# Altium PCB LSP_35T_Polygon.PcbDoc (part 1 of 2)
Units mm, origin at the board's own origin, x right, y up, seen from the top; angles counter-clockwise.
Board outline 152.4 x 101.6 mm, 4 copper layers (Top Layer, Mid-Layer 1, Mid-Layer 3, Bottom Layer); 138 components, 96 nets, 424 pads, 124 vias.
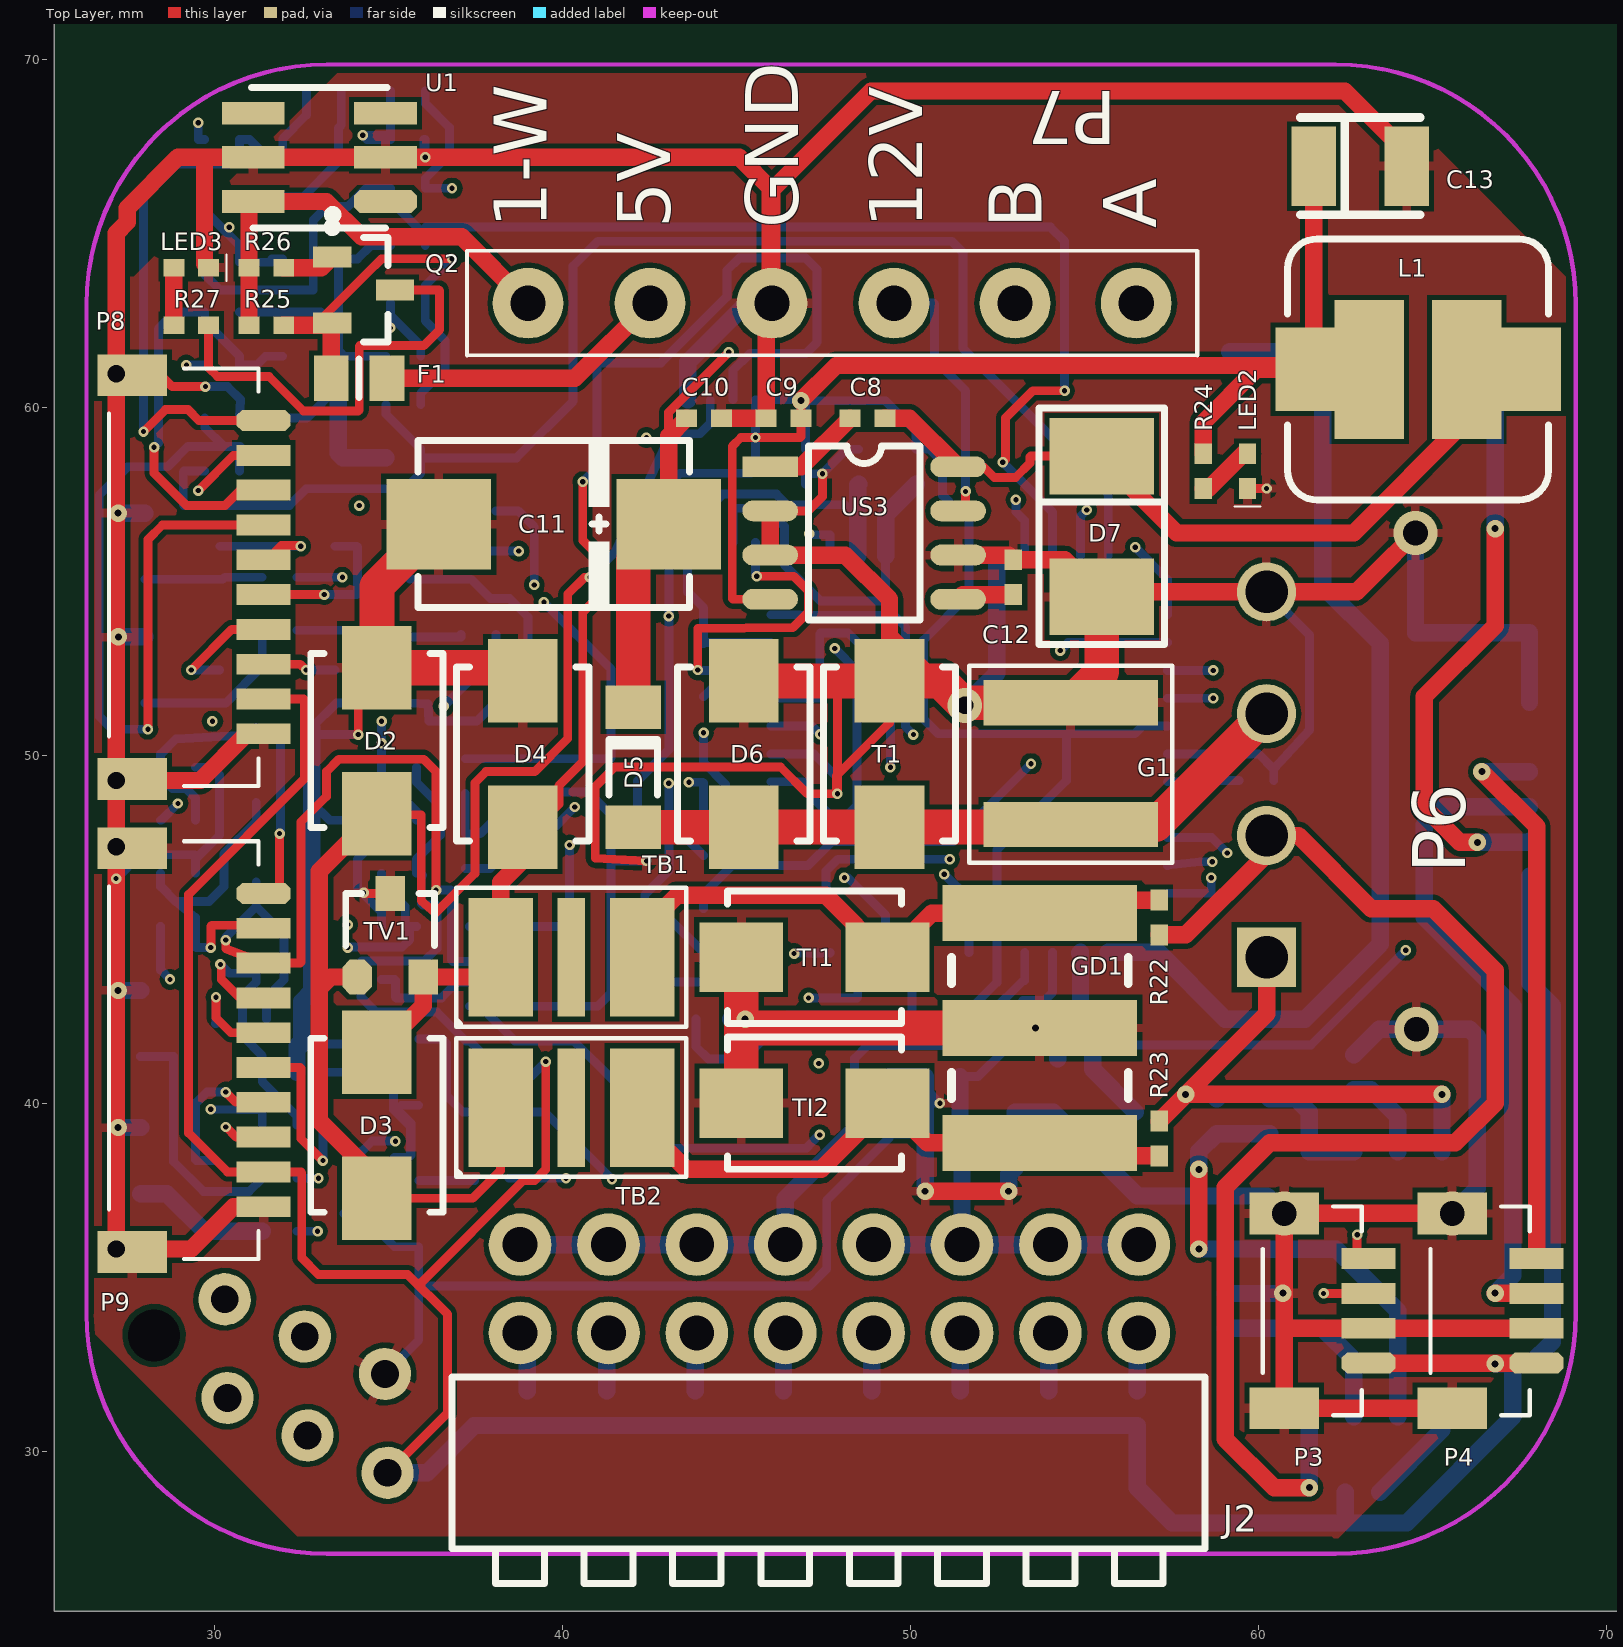
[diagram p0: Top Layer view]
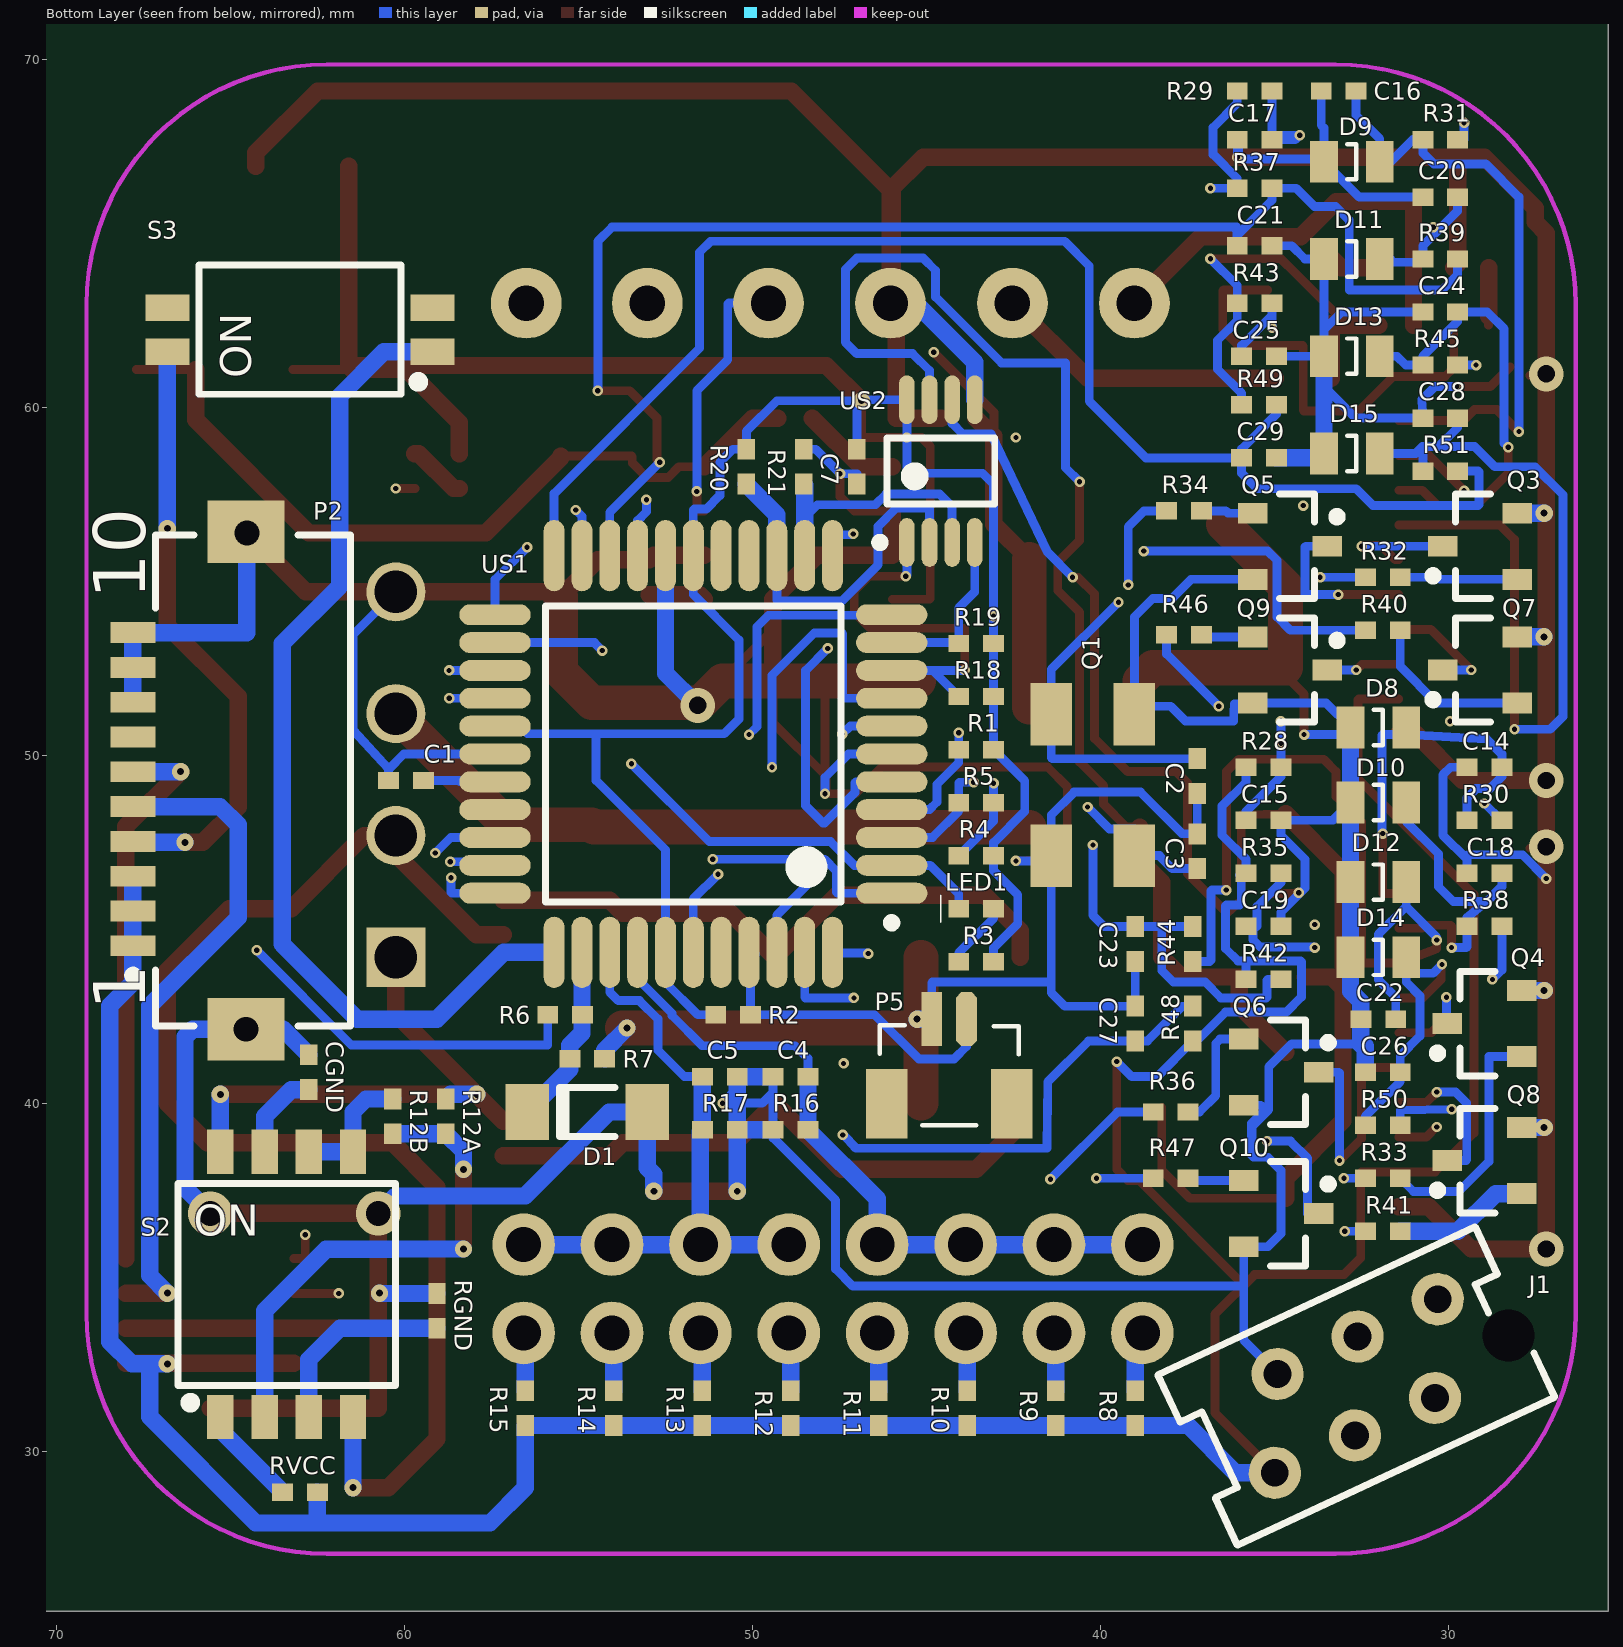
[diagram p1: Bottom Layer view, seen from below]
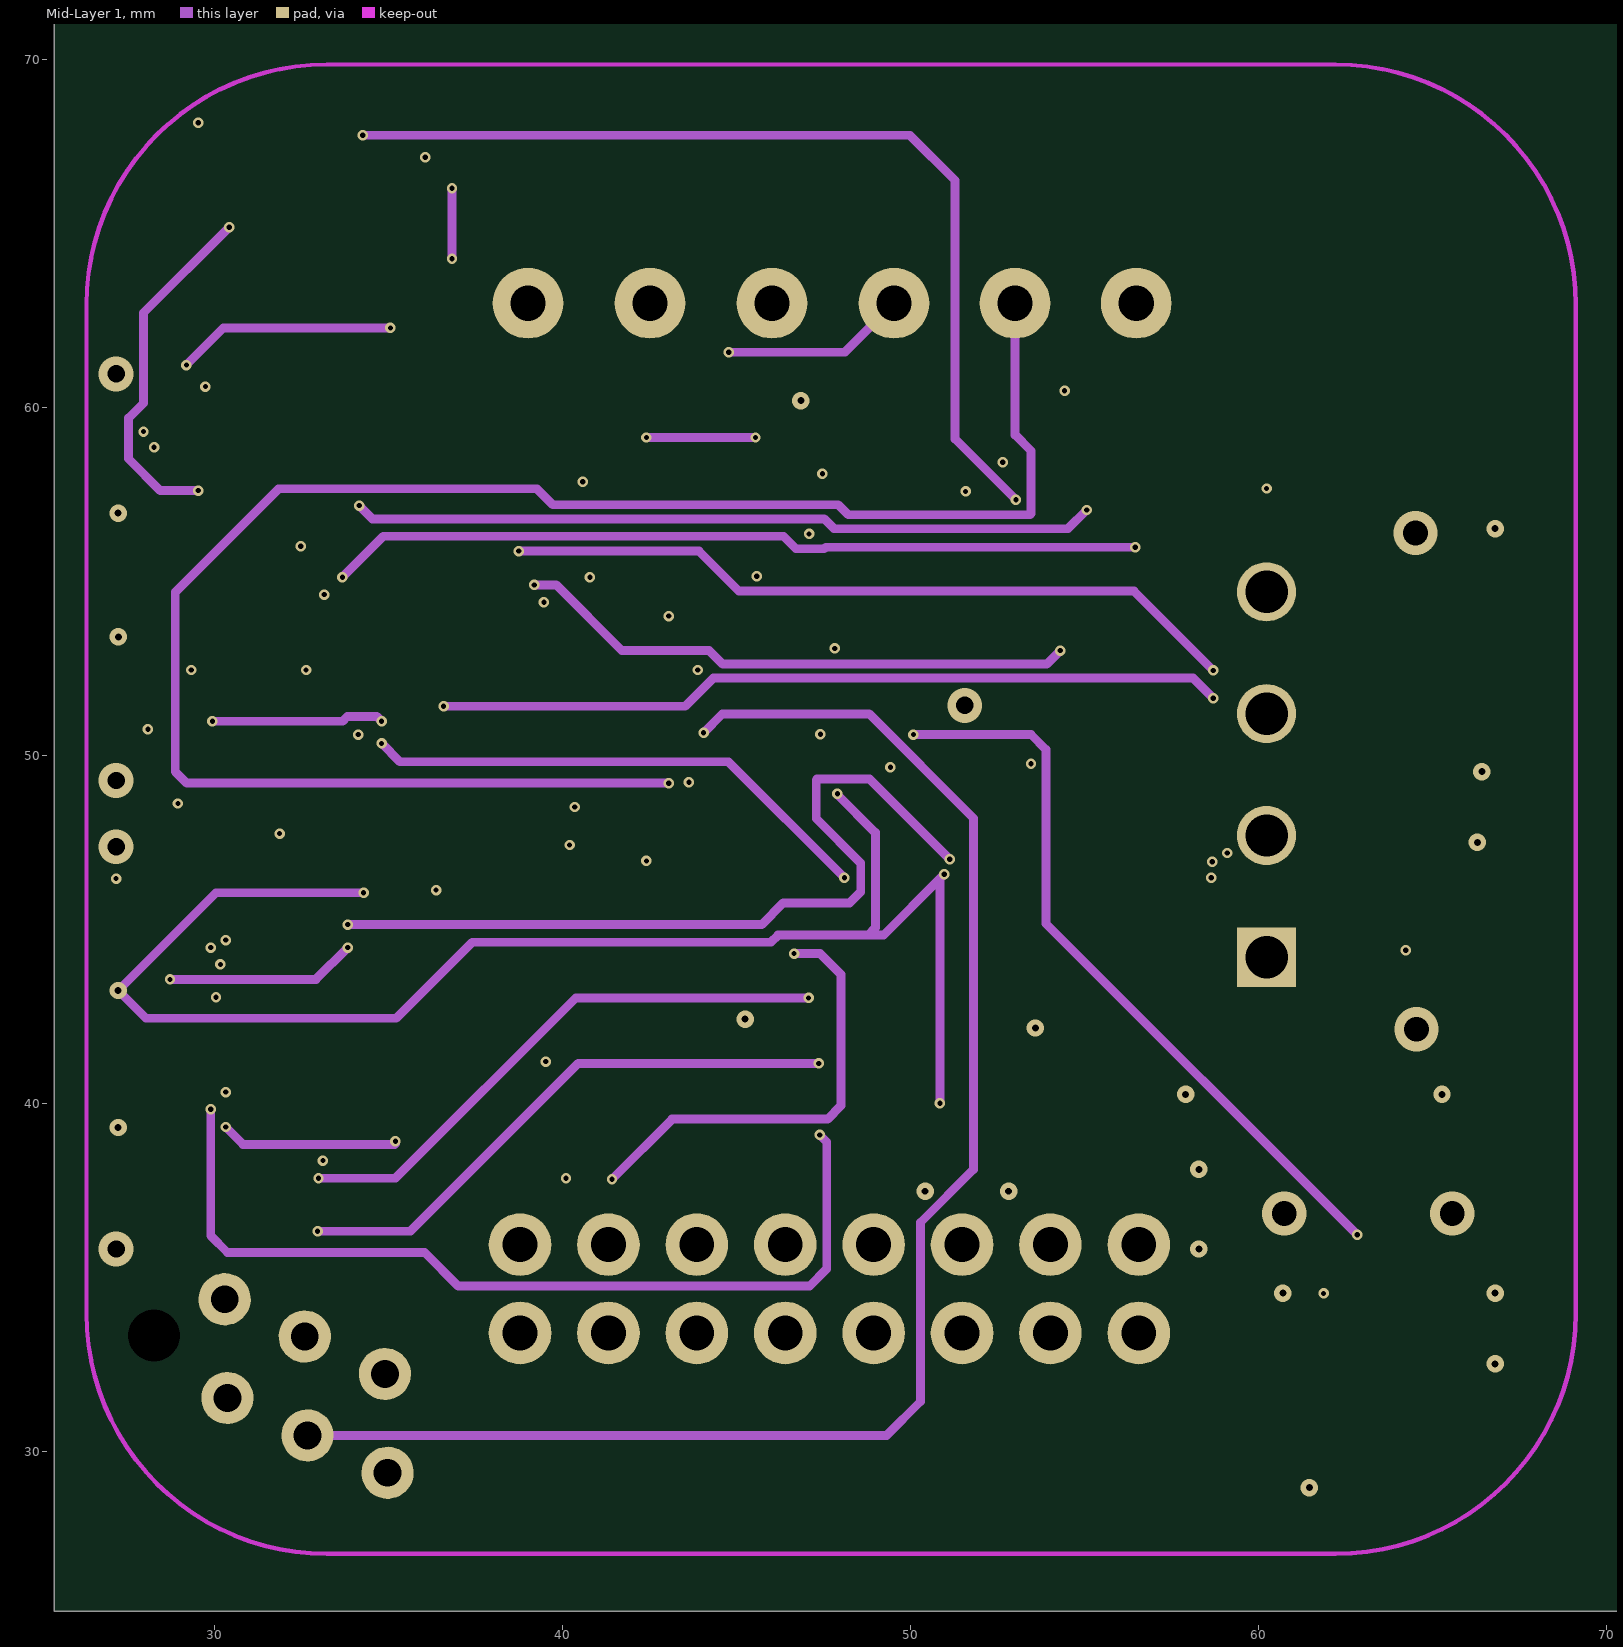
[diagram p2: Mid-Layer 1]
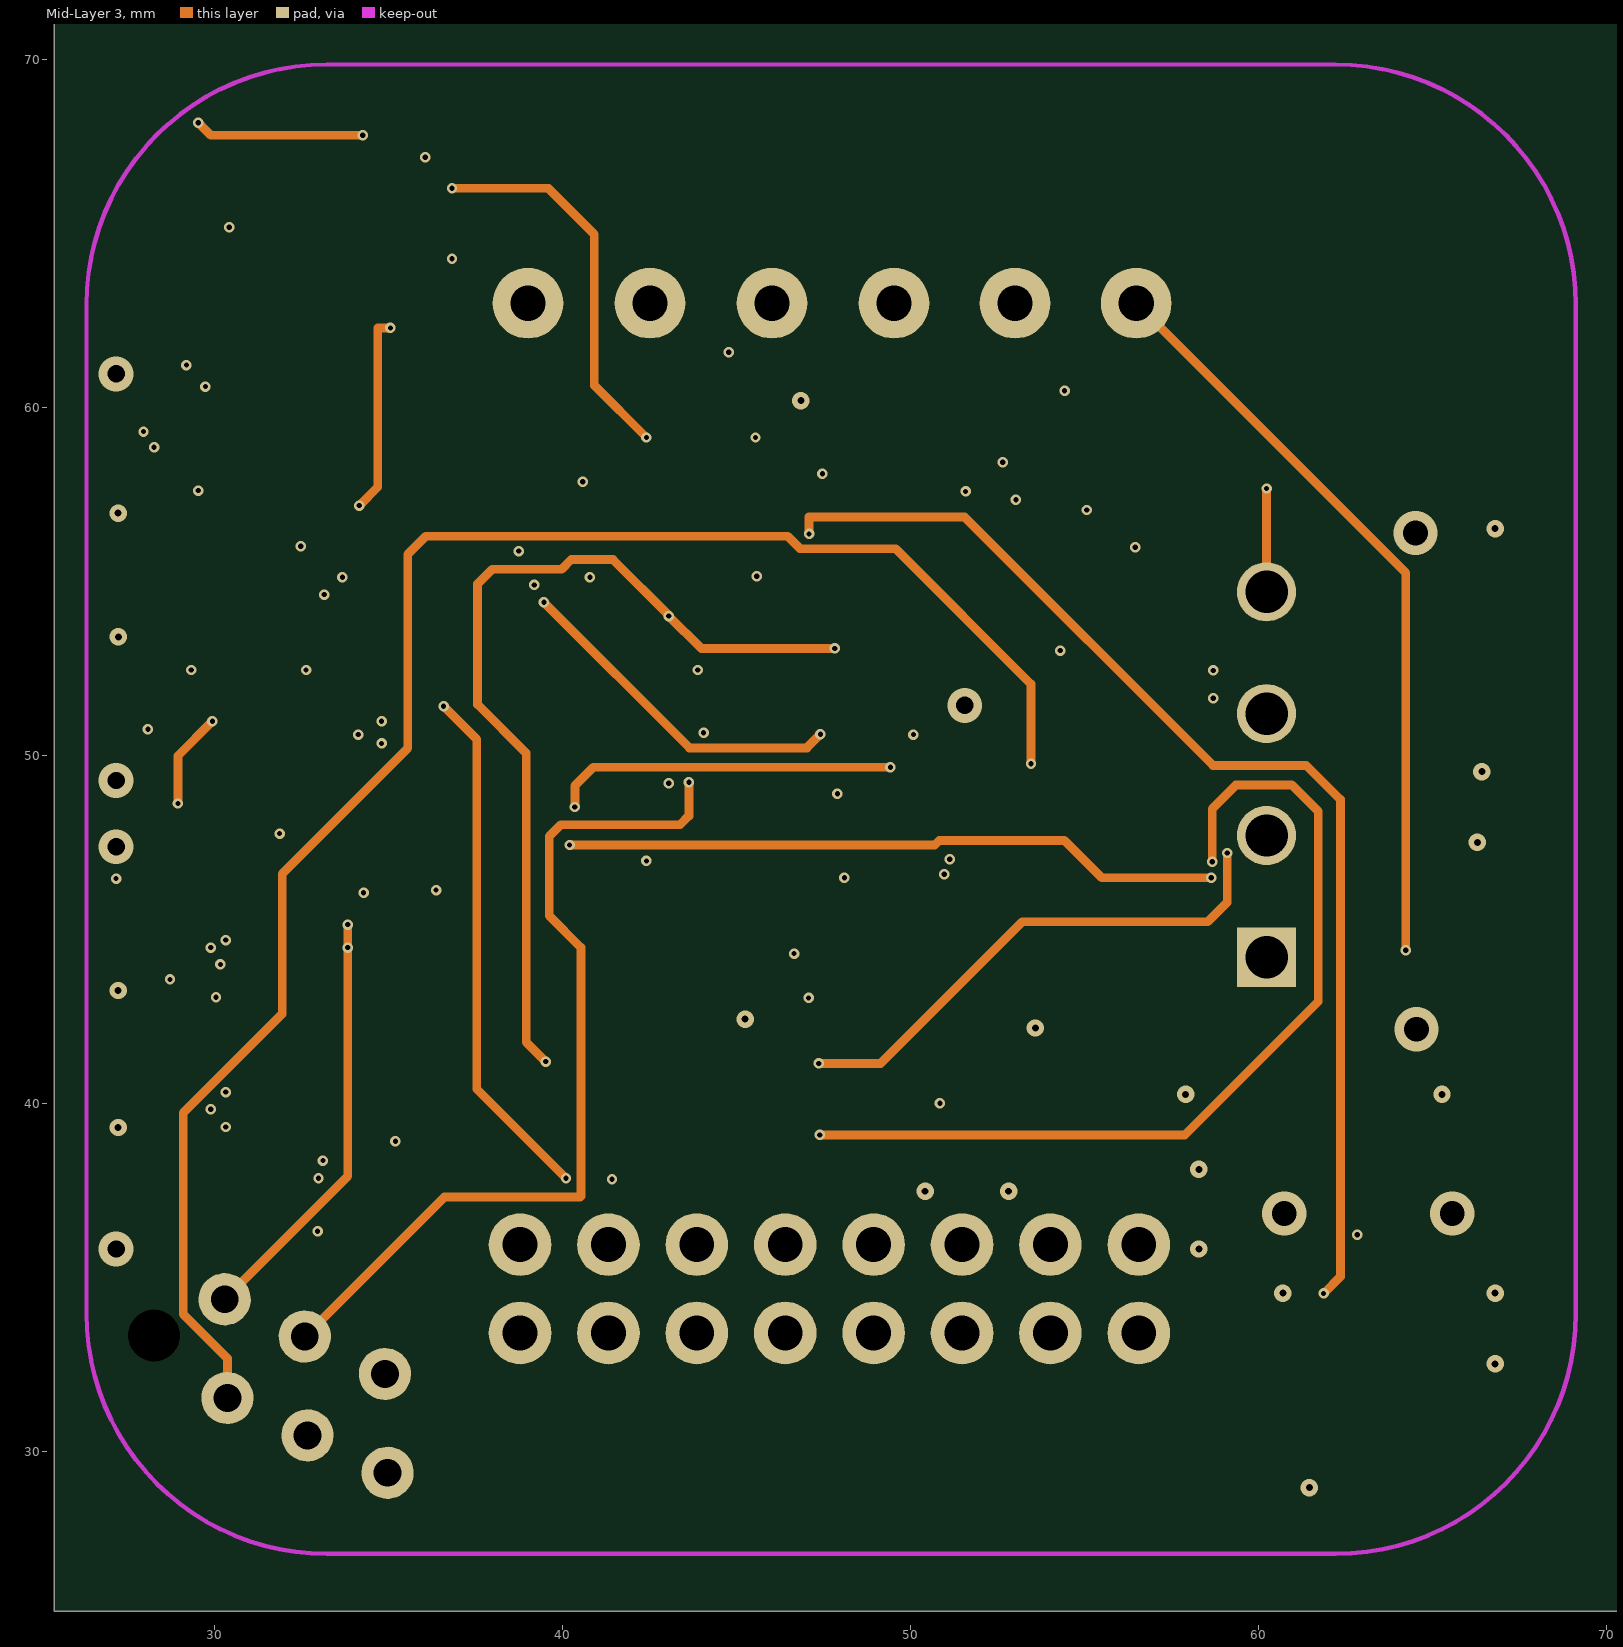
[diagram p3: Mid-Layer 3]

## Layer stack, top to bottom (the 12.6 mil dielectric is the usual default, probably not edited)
Top Layer: signal copper 0.0356
Dielectric: dielectric 0.32, FR-4, Dk 4.8
Mid-Layer 1: signal copper 0.0356
Dielectric: dielectric 0.32, FR-4, Dk 4.8
Mid-Layer 3: signal copper 0.0356
Dielectric: dielectric 0.32, FR-4, Dk 4.8
Bottom Layer: signal copper 0.0356

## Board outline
25.4,25.4 177.8,25.4 177.8,127 25.4,127

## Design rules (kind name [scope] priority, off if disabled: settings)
Clearance [All] p1: gap=0.15
ComponentClearance [All] p1: gap=0.15 collisioncheckmode=3 verticalgap=0.254 showdistances=FALSE
MinimumSolderMaskSliver [All] p1: minsoldermaskwidth=0.15
PolygonConnect [All] p1: connectstyle=Relief reliefconductorwidth=0.254 reliefentries=4 polygonreliefangle="90 Angle"
RoutingVias [All] p1: holewidth=0.15 width=0.3 viastyle="Through Hole" minholewidth=0.15 minwidth=0.3 maxholewidth=1.2 maxwidth=1.5
SilkToSilkClearance [All] p1: silktosilkclearance=0
SilkscreenOverComponentPads [All] p1: minsilkscreentomaskgap=0
SolderMaskExpansion [All] p1: expansion=0.1
Width [All] p1: maxlimit=1 minlimit=0.15 preferedwidth=0.254
24 further rules are at their usual default settings.

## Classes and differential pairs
component class LSP_DIO: C14 C15 C16 C17 C18 C19 C20 C21 C22 C23 C24 C25 C26 C27 C28 C29 D8 D9 D10 D11 D12 D13 D14 D15 P8 P9 Q3 Q4 Q5 Q6 Q7 Q8 Q9 Q10 R28 R29 R30 R31 R32 R33 R34 R35 R36 R37 R38 R39 R40 R41 R42 R43 R44 R45 R46 R47 R48 R49 R50 R51
component class ZASILACZ: C8 C9 C10 C11 C12 C13 D5 D6 D7 G1 L1 LED2 R24 T1 US3
component class RS485: C7 CGND D2 D3 D4 GD1 R12A R12B R18 R19 R20 R21 R22 R23 RGND RVCC S2 TB1 TB2 TI1 TI2 TV1 US2
component class LSP_35T: C1 C2 C3 D1 J1 LED1 P2 P3 P4 P5 P6 Q1 R1 R2 R3 R4 R5 R6 R7 S3 US1
component class Adres: C4 C5 J2 R8 R9 R10 R11 R12 R13 R14 R15 R16 R17
component class 1-Wire: F1 LED3 P7 Q2 R25 R26 R27 U1

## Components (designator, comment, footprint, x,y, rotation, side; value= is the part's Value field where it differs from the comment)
C1 "10nF/16V (X7R)" 0402 59.944,49.276 r0 bottom
C2 "15pF/16V (NPO)" 0402 37.211,49.403 r90 bottom
C3 "15pF/16V (NPO)" 0402 37.211,47.244 r270 bottom
C4 "100nF/16V (X7R)" 0402 48.895,40.767 r0 bottom
C5 "100nF/16V (X7R)" 0402 50.927,40.767 r180 bottom
C7 "100nF/16V (X7R)" 0402 46.99,58.293 r90 bottom
C8 "10nF/50V (X7R)" 0402 48.768,59.69 r0 top
C9 "100nF/25V (X7R)" 0402 46.355,59.69 r0 top
C10 "100nF/50V (X7R)" 0402 44.069,59.69 r180 top
C11 "22uF/35V" SMD_C_TANTAL-D 43.053,56.642 r180 top
C12 "100nF/50V (X7R)" 0402 52.959,55.118 r270 top
C13 "T491B226M010AT" TANTAL-B 61.595,66.929 r0 top
C14 "Cap Semi" 0402 28.956,49.657 r180 bottom
C15 "Cap Semi" 0402 35.306,48.133 r0 bottom
C16 "Cap Semi" 0402 33.147,69.088 r180 bottom
C17 "Cap Semi" 0402 35.56,67.691 r180 bottom
C18 "Cap Semi" 0402 28.956,46.609 r180 bottom
C19 "Cap Semi" 0402 35.306,45.085 r0 bottom
C20 "Cap Semi" 0402 30.226,66.04 r180 bottom
C21 "Cap Semi" 0402 35.56,64.643 r0 bottom
C22 "Cap Semi" 0402 32.004,42.418 r180 bottom
C23 "Cap Semi" 0402 38.989,44.577 r90 bottom
C24 "Cap Semi" 0402 30.226,62.738 r180 bottom
C25 "Cap Semi" 0402 35.433,61.468 r0 bottom
C26 "Cap Semi" 0402 31.877,40.894 r180 bottom
C27 "Cap Semi" 0402 38.989,42.291 r270 bottom
C28 "Cap Semi" 0402 30.226,59.69 r180 bottom
C29 "Cap Semi" 0402 35.433,58.547 r0 bottom
CGND "220pF/16V (X7R)" 0402 62.738,40.894 r270 bottom
D1 "D Zener" minimelf 54.737,39.751 r0 bottom
D2 "P6SMB33CA" SMD_DO-214AA/SMB 34.671,50.419 r90 top
D3 "P6SMB33CA" SMD_DO-214AA/SMB 34.671,39.37 r90 top
D4 "P6SMB33CA" SMD_DO-214AA/SMB 38.862,50.038 r270 top
D5 "GL1M" minimelf 42.037,49.657 r90 top
D6 "P6SMB33CA" SMD_DO-214AA/SMB 45.212,50.038 r270 top
D7 "LL5819" SMD_MELF2 55.499,54.229 r90 top
D8 "BZM55B5V" MicroMELF 32.004,50.8 r180 bottom
D9 "BZM55B5V" MicroMELF 32.766,67.056 r180 bottom
D10 "BZM55B5V" MicroMELF 32.004,48.641 r180 bottom
D11 "BZM55B5V" MicroMELF 32.766,64.262 r180 bottom
D12 "BZM55B5V" MicroMELF 32.004,46.355 r180 bottom
D13 "BZM55B5V" MicroMELF 32.766,61.468 r180 bottom
D14 "BZM55B5V" MicroMELF 32.004,44.196 r180 bottom
D15 "BZM55B5V" MicroMELF 32.766,58.674 r180 bottom
F1 "ERFSR010" 6-0805_L 34.163,60.833 r0 top
G1 "GDT2053-07-SM" GDT2053 54.61,48.006 r90 top
GD1 "GDT2038-15-SM-RPLF" GDT2038 53.721,45.466 r270 top
J1 "7-215079-6" PRZ_MICROMATCH-6 32.639,31.877 r155 bottom
J2 "SW DIP-8" DIP8 38.786,33.401 r90 top locked
L1 "SCDS74T-470M-S" SMD_SCDS74T 67.691,61.087 r0 top
LED1 "KP-2012ID" 0402d 43.561,45.593 r0 bottom
LED2 "KP-2012SGC" 0402D 59.69,58.166 r270 top
LED3 "KPG-1005VGC-TT" 0402D 29.337,64.008 r0 top
P2 "Header 10" FFC/SM1.0-2H10 66.167,49.276 r90 bottom
P3 "665304124022" 665304124022 63.17,34.036 r90 top
P4 "665304124022" 665304124022 67.996,34.036 r90 top
P5 "Header 2" 665302124022 45.339,42.418 r0 bottom
P6 "MKDSO 1,5/4 L" FK-MPT05/4-ICA-35 60.237,44.197 r90 top locked
P7 "Header 6" PT1,5/6-PVH-3,5 53.01,62.992 r0 top
P8 "665 110 131 822" 665110131822 31.42,55.118 r270 top locked
P9 "665 110 131 822" 665110131822 31.42,41.529 r270 top locked
Q1 "11.0592MHZ" ABM3B 41.402,47.117 r90 bottom
Q2 "BC857" NXP-SOT23_L 34.29,63.373 r0 top
Q3 "BC847C" SOT23_L 29.083,56.007 r0 bottom
Q4 "BC847C" SOT23_L 28.956,42.291 r0 bottom
Q5 "BC847C" SOT23_L 34.544,56.007 r180 bottom
Q6 "BC847C" SOT23_L 34.798,40.894 r180 bottom
Q7 "BC847C" SOT23_L 29.083,52.451 r0 bottom
Q8 "BC847C" SOT23_L 28.956,38.354 r0 bottom
Q9 "BC847C" SOT23_L 34.544,52.451 r180 bottom
Q10 "BC847C" SOT23_L 34.798,36.83 r180 bottom
R1 "10k 1%" 0402 43.561,50.165 r180 bottom
R2 "1k5 1%" 0402 50.546,42.545 r180 bottom
R3 "1k 1%" 0402 43.561,44.069 r0 bottom
R4 "10k 1%" 0402 43.561,47.117 r180 bottom
R5 "100k 1%" 0402 43.561,48.641 r180 bottom
R6 "10k 1%" 0402 55.372,42.545 r0 bottom
R7 "10k 1%" 0402 54.737,41.275 r0 bottom
R8 "82k 1%" 0402 38.989,31.242 r90 bottom
R9 "39k 1%" 0402 41.275,31.242 r90 bottom
R10 "20k 1%" 0402 43.815,31.242 r90 bottom
R11 "10k 1%" 0402 46.355,31.242 r90 bottom
R12 "82k 1%" 0402 48.895,31.242 r90 bottom
R12A "60ohm 1%" 0402 58.801,39.624 r270 bottom
R12B "60ohm 1%" 0402 60.325,39.624 r270 bottom
R13 "39k 1%" 0402 51.435,31.242 r90 bottom
R14 "20k 1%" 0402 53.975,31.242 r90 bottom
R15 "10k 1%" 0402 56.515,31.242 r90 bottom
R16 "4k7 1%" 0402 48.895,39.243 r0 bottom
R17 "4k7 1%" 0402 50.927,39.243 r180 bottom
R18 "4k7 1%" 0402 43.561,51.689 r0 bottom
R19 "4k7 1%" 0402 43.561,53.213 r0 bottom
R20 "4k7 1%" 0402 50.165,58.293 r90 bottom
R21 "4k7 1%" 0402 48.514,58.293 r90 bottom
R22 "1ohm 1%" 0402 57.15,45.339 r270 top
R23 "1ohm 1%" 0402 57.15,38.989 r90 top
R24 "330 ohm 1%" 0402 58.42,58.166 r270 top
R25 "" 0402 31.496,62.357 r0 top
R26 "" 0402 31.496,64.008 r0 top
R27 "" 0402 29.337,62.357 r0 top
R28 "100k 1%" 0402 35.306,49.657 r0 bottom
R29 "100k 1%" 0402 35.56,69.088 r0 bottom
R30 "15k 1%" 0402 28.956,48.133 r180 bottom
R31 "15k 1%" 0402 30.226,67.691 r180 bottom
R32 "5k1 1%" 0402 31.877,55.118 r0 bottom
R33 "5k1 1%" 0402 31.877,37.846 r0 bottom
R34 "5k1 1%" 0402 37.592,57.023 r0 bottom
R35 "100k 1%" 0402 35.306,46.609 r0 bottom
R36 "5k1 1%" 0402 37.973,39.751 r0 bottom
R37 "100k 1%" 0402 35.56,66.294 r0 bottom
R38 "15k 1%" 0402 28.956,45.085 r180 bottom
R39 "15k 1%" 0402 30.226,64.262 r180 bottom
R40 "5k1 1%" 0402 31.877,53.594 r0 bottom
R41 "5k1 1%" 0402 31.877,36.322 r0 bottom
R42 "100k 1%" 0402 35.306,43.561 r0 bottom
R43 "100k 1%" 0402 35.56,62.992 r0 bottom
R44 "15k 1%" 0402 37.338,44.577 r90 bottom
R45 "15k 1%" 0402 30.226,61.214 r180 bottom
R46 "5k1 1%" 0402 37.592,53.467 r0 bottom
R47 "5k1 1%" 0402 37.973,37.846 r0 bottom
R48 "100k 1%" 0402 37.338,42.291 r270 bottom
R49 "100k 1%" 0402 35.433,60.071 r0 bottom
R50 "15k 1%" 0402 31.877,39.37 r180 bottom
R51 "15k 1%" 0402 30.226,58.166 r180 bottom
RGND "540ohm 1%" 0402 59.055,34.036 r270 bottom
RVCC "540om 1%" 0402 62.992,28.829 r0 bottom
S2 "SW-DIP4" 416131160804 63.373,34.798 r180 bottom
S3 "SW-SPST" 416131160802 62.992,62.23 r90 bottom
T1 "TISP4240M3BJR-S" SMD_DO-214AA/SMB 49.403,50.038 r90 top
TB1 "TBU-CA065-200-WH" TBU-CA 38.227,44.196 r0 top
TB2 "TBU-CA065-200-WH" TBU-CA 38.227,39.878 r0 top
TI1 "TISP4240M3BJR-S" SMD_DO-214AA/SMB 47.244,44.196 r180 top
TI2 "TISP4240M3BJR-S" SMD_DO-214AA/SMB 47.244,40.005 r180 top
TV1 "TVS CDS0T23-SM712" SOT23 35.052,44.831 r0 top
U1 "DS9503P+" TSOC6 33.02,67.183 r90 top
US1 "ATMEGA1284-MU" 44A_M 51.689,50.038 r0 bottom
US2 "SN65HVD485EDGK" DGK8_L 44.577,58.166 r90 bottom
US3 "LM2674_5.0" SMD_SO-8 45.974,58.293 r270 top

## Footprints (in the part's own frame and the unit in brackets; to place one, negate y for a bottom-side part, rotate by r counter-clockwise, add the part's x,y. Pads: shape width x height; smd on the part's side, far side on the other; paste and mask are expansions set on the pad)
6-0805_L [mm] "Chip Resistor, Body 2.0x1.2mm, IPC High Density"
  rect 1x1.3 smd: 1(-0.8,0) 2(0.8,0)
  silkscreen extent 0,-0.55 0,0.55, body extent -1.07,-0.7 1.07,0.7, height 0.7
44A_M [mm] "Thin QFP, 44-Leads, Body 10x10mm, Pitch 0.8mm, IPC Low Density"
  oval 2.05x0.6 smd: 1(-5.7,4) 2(-5.7,3.2) 3(-5.7,2.4) 4(-5.7,1.6) 5(-5.7,0.8) 6(-5.7,0) 7(-5.7,-0.8) 8(-5.7,-1.6) 9(-5.7,-2.4) 10(-5.7,-3.2) 11(-5.7,-4) 23(5.7,-4) 24(5.7,-3.2) 25(5.7,-2.4) 26(5.7,-1.6) 27(5.7,-0.8) 28(5.7,0) 29(5.7,0.8) 30(5.7,1.6) 31(5.7,2.4) 32(5.7,3.2) 33(5.7,4)
  oval 0.6x2.05 smd: 12(-4,-5.7) 13(-3.2,-5.7) 14(-2.4,-5.7) 15(-1.6,-5.7) 16(-0.8,-5.7) 17(0,-5.7) 18(0.8,-5.7) 19(1.6,-5.7) 20(2.4,-5.7) 21(3.2,-5.7) 22(4,-5.7) 34(4,5.7) 35(3.2,5.7) 36(2.4,5.7) 37(1.6,5.7) 38(0.8,5.7) 39(0,5.7) 40(-0.8,5.7) 41(-1.6,5.7) 42(-2.4,5.7) 43(-3.2,5.7) 44(-4,5.7)
  silkscreen extent -5.82,-4.25 4.25,4.97, body extent -5,-5 5,5, height 1.2
0402 [mm] "Chip Capacitor, Body 1.0x0.5mm, IPC High Density"
  rect 0.6x0.5 smd: 1(-0.5,0) 2(0.5,0)
  body extent -0.55,-0.3 0.55,0.3, height 1.3
0402d [mm] "Diode, Body 1.0x0.5mm, IPC High Density"
  rect 0.6x0.5 smd: 1(-0.5,0) 2(0.5,0)
  silkscreen extent 1.02,-0.38 1.02,0.38
0402D [mm] "Diode, Body 1.0x0.5mm, IPC High Density"
  rect 0.6x0.5 smd: 1(-0.5,0) 2(0.5,0)
  silkscreen extent 1.02,-0.38 1.02,0.38
416131160802 [mm] "1.27 mm small compact SMD flat actuator with top tape, 02p"
  rect 0.76x1.27 smd: 1(-0.635,-3.81) 2(-0.635,3.81) 3(0.635,-3.81) 4(0.635,3.81)
  silkscreen extent -1.86,-3.43 1.86,2.9, body extent -1.85,-4.22 1.86,4.22, height 2.7
416131160804 [mm] "1.27 mm small compact SMD flat actuator with top tape, 04p"
  rect 0.76x1.27 smd: 1(-1.905,-3.81) 2(-0.635,-3.81) 3(0.635,-3.81) 4(1.905,-3.81) 5(1.905,3.81) 6(0.635,3.81) 7(-0.635,3.81) 8(-1.905,3.81)
  silkscreen extent -3.13,-3.43 3.13,2.9, body extent -3.12,-4.22 3.13,4.22, height 2.7
665110131822 [mm] "ConWTB Wire-to-Board Connectors 1.00 mm SMT Male Horizontal Shrouded Header, 10 pins - Tape & Reel"
  oct 0.6x1.55 smd: 1(-4.5,0)
  rect 0.6x1.55 smd: 2(-3.5,0) 3(-2.5,0) 4(-1.5,0) 5(-0.5,0) 6(0.5,0) 7(1.5,0) 8(2.5,0) 9(3.5,0) 10(4.5,0)
  rect 1.2x2 smd: Z1(-5.8,-3.775) Z2(5.8,-3.775)
  silkscreen extent -6,-4.45 6,-0.15, body extent -6,-4.4 6,0.55, height 2.95
665302124022 [mm] "ConWTB Wire-to-Board Connectors 1.00 mm SMT Male Vertical Shrouded Header, 4 pins - Tape & Reel with Cap"
  oct 0.6x1.55 smd: 1(-1.5,0)
  rect 0.6x1.55 smd: 2(-0.5,0)
  rect 1.2x2 smd: Z1(-2.8,2.425) Z2(0.793,2.425)
  silkscreen extent -3,0.17 0.99,3.05
665304124022 [mm] "ConWTB Wire-to-Board Connectors 1.00 mm SMT Male Vertical Shrouded Header, 4 pins - Tape & Reel with Cap"
  oct 0.6x1.55 smd: 1(-1.5,0)
  rect 0.6x1.55 smd: 2(-0.5,0) 3(0.5,0) 4(1.5,0)
  rect 1.2x2 smd: Z1(-2.8,2.425) Z2(2.8,2.425)
  silkscreen extent -3,0.2 3,3.05, body extent -3,-0.9 3,3.6, height 5.09
ABM3B [mil]
  rect 71x47 smd: 1(0,-94) 2(160,0) GND(0,0) GND(160,-94)
DGK8_L [mm] "TSOP, 8-Leads, Body 3x3mm, Pitch 0.65mm, IPC High Density"
  oval 1.4x0.45 smd: 1(-2.05,0.975) 2(-2.05,0.325) 3(-2.05,-0.325) 4(-2.05,-0.975) 5(2.05,-0.975) 6(2.05,-0.325) 7(2.05,0.325) 8(2.05,0.975)
  silkscreen extent -2.17,-1.55 0.95,1.88, body extent -1.55,-1.55 1.55,1.55, height 1.1
DIP8 [mm]
  round 1.8 hole 1: 1(0,0) 2(0,-2.54) 3(0,-5.08) 4(0,-7.62) 5(0,-10.16) 6(0,-12.7) 7(0,-15.24) 8(0,-17.78) 9(2.54,-17.78) 10(2.54,-15.24) 11(2.54,-12.7) 12(2.54,-10.16) 13(2.54,-7.62) 14(2.54,-5.08) 15(2.54,-2.54) 16(2.54,0)
  silkscreen extent -7.2,-19.68 -1.27,1.95
FFC/SM1.0-2H10 [mm] "Connector; FH12 Series; 10 Position; 1.0mm Spaced Bottom Eccentric Contact"
  rect 0.6x1.3 smd: 1(-4.75,1.625) 2(-3.75,1.625) 3(-2.75,1.625) 4(-1.75,1.625) 5(-0.75,1.625) 6(0.25,1.625) 7(1.25,1.625) 8(2.25,1.625) 9(3.25,1.625) 10(4.25,1.625)
  rect 1.8x2.2 smd: 11(7.15,-1.625) 12(-7.15,-1.625)
  silkscreen extent -7.05,-4.62 7.05,1.75, body extent -7.05,-4.62 7.05,0.97, height 2
FK-MPT05/4-ICA-35 [mm]
  rect 1.7x1.7 hole 1.219: 1(0,0)
  round 1.7 hole 1.219: 2(3.5,0) 3(7,0) 4(10.5,0)
GDT2038 [mil]
  rect 63x220 smd: 1(0,0) 2(260,0) 3(130,0)
  silkscreen extent 50,-100 210,100
GDT2053 [mil]
  rect 51x197 smd: 1(0,0) 2(138,0)
  silkscreen extent -43,-115 180,115
MicroMELF [mil]
  rect 31.5x47.3 smd: 1(-31.5,0) 2(31.5,0)
  silkscreen extent -5,-20 5,20
minimelf [mm] "Metal Electrode Face (MELF) Diode; Body 3.5 x 1.5 mm (LxDia)"
  rect 1.25x1.6 smd: 1(-1.725,0) 2(1.725,0)
  silkscreen extent -0.8,-0.7 0.8,0.7
NXP-SOT23_L [mm] "SOT23, 3-Leads, Body 3x1.4mm, Pitch 0.95mm, IPC High Density"
  rect 1.1x0.6 smd: 1(-0.9,0.95) 2(-0.9,-0.95) 3(0.9,0)
  silkscreen extent -1.02,-1.5 0.7,1.92, body extent -0.7,-1.5 0.7,1.5, height 1.1
PRZ_MICROMATCH-6 [mm]
  round 1.5 hole 0.8: 1(3.175,1.27) 2(1.905,-1.27) 3(0.635,1.27) 4(-0.635,-1.27) 5(-1.905,1.27) 6(-3.175,-1.27)
  round 0.8 hole 1.5: ""(4.575,-0.53)
  silkscreen extent -5.03,-2.7 5.03,2.7
PT1,5/6-PVH-3,5 [mil] "Phoenix Contact Terminal"
  round 80 hole 40: 1(-551,0) 2(-413,0) 3(-275,0) 4(-137,0) 5(0,0) 6(137,0)
  silkscreen extent -620,-59 206,59
SMD_C_TANTAL-D [mm]
  rect 3x2.6 smd: 1(0,0) 2(6.6,0)
  silkscreen extent -0.6,-2.4 7.2,2.4
SMD_DO-214AA/SMB [mm]
  rect 2.4x2 smd: 1(-2.1,0) 2(2.1,0)
  silkscreen extent -2.5,-1.9 2.5,1.9
SMD_MELF2 [mm]
  rect 2.2x3 smd: 1(0.33,0) 2(4.369,0)
  silkscreen extent -1.05,-1.8 5.75,1.8
SMD_SCDS74T [mm]
  rect 2x4 smd: 1(-1.7,0) 2(-4.5,0)
  rect 2x2.4 smd: 1(0,0) 2(-6.2,0)
  silkscreen extent -6.85,-3.75 0.65,3.75
SMD_SO-8 [mm]
  rect 0.6x1.6 smd: 1(0,0)
  oval 0.6x1.6 smd: 2(1.27,0) 3(2.54,0) 4(3.81,0) 5(3.81,5.4) 6(2.54,5.4) 7(1.27,5.4) 8(0,5.4)
  silkscreen extent -0.6,1.1 4.41,4.3
SOT23 [mm] "SOT-23; 3 Leads; Body 3.0 x 2.5 mm, inc. leads (LxW max)"
  oct 0.85x1 smd: 1(-0.95,-1.2)
  rect 0.85x1 smd: 2(0.95,-1.2) 3(0,1.2)
  silkscreen extent -1.27,-0.3 1.28,1.2
SOT23_L [mm] "SOT23, 3-Leads, Body 2.9x1.3mm, Pitch 0.95mm, Lead Span 2.3mm - Reverse Pinning, IPC High Density"
  rect 0.85x0.6 smd: 1(1.075,0) 2(-1.075,-0.95) 3(-1.075,0.95)
  silkscreen extent -0.3,-1.5 1.48,1.5, body extent -0.7,-1.5 0.7,1.5, height 1.1
TANTAL-B [mil]
  rect 50x90 smd: 1(0,0) 2(105,0)
  silkscreen extent -15,-55 120,55
TBU-CA [mil]
  rect 31x134 smd: 0(80,0)
  rect 73x134 smd: 1(0,0) 2(160,0)
  silkscreen extent -50,-78 210,78
TSOC6 [mm] "Small Outline; 6 C-Bend Leads; Body Width 3.8 mm; Pitch 1.27 mm"
  oct 0.65x1.8 smd: 1(-1.27,-1.9)
  rect 0.65x1.8 smd: 2(0,-1.9) 3(1.27,-1.9) 4(1.27,1.9) 5(0,1.9) 6(-1.27,1.9)
  silkscreen extent -2.03,-1.95 2,1.95

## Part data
C1 C2 C3 C4 C5 C7 C8 C9 C10 C12 CGND: library part _C_CER, "Ceramic capacitor"
C11: library part CAP2, "Bi-Polar Capacitor"
C13: library part "Cap Pol1", "Polarized Capacitor (Radial)"
C14 C15 C16 C17 C18 C19 C20 C21 C22 C23 C24 C25 C26 C27 C28 C29: "Capacitor (Semiconductor SIM Model)"
D1: "Zener Diode"
D2 D3 D4 D6: "Transil diode 600W 33V bidirectional"
D5 D7: library part DIODA1, "Dioda"
D8 D9 D10 D11 D12 D13 D14 D15: library part "D Zener", "Zener Diode"
F1: library part "Fuse 1", "Fuse"
G1: library part GDT_1
GD1: library part GDT
J2: "DIP Switch, 8 Position, SPST"
L1: library part CEWKA2
LED1 LED2: library part DIODA2, "Dioda LED"
LED3: library part LED2, "Typical RED, GREEN, YELLOW, AMBER GaAs LED"
P2: "Header, 10-Pin"
P3 P4 P6: library part "Header 4", "Header, 4-Pin"
P5: "Header, 2-Pin"
P7: "Header, 6-Pin"
P8 P9: library part "Header 10", "Header, 10-Pin"
Q1: "Quartz 11,0592MHz, height 3,5mm"
Q2: library part 2N3906, "PNP General Purpose Amplifier"
Q3 Q4 Q5 Q6 Q7 Q8 Q9 Q10: library part 2N3904, "NPN General Purpose Amplifier"
R1 R2 R3 R4 R5 R6 R7 R8 R9 R10 R11 R12 R12A R12B R13 R14 R15 R16 R17 R18 R19 R20 R21 R22 R23 R24 RGND RVCC: library part RESSMD1, "Rezystor"
R25 R26 R27 R28 R29 R30 R31 R32 R33 R34 R35 R36 R37 R38 R39 R40 R41 R42 R43 R44 R45 R46 R47 R48 R49 R50 R51: library part Res3, "Resistor"
S2: "DIP Switch"
S3: "Single-Pole, Single-Throw Switch"
T1 TI1 TI2: library part TISP, "Tisp"
TB1 TB2: library part TBU, "TBU"
TV1: library part TVS
U1: library part "Header 3X2", "Header, 3-Pin, Dual row"
US1: library part ATMEGA1284-AU
US2: "Half Duplex RS-485 Transceiver, 10 Mbps, 5 V, -40 to 85 degC, 8-pin MSOP (DGK), Green (RoHS & no Sb/Br)"
US3: library part LM2675

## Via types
v1: diameter 0.3, hole 0.15, Top Layer to Bottom Layer, tented both sides, 95 vias
v2: diameter 0.5, hole 0.2, Top Layer to Bottom Layer, tented both sides, 20 vias
v3: diameter 1, hole 0.5, Top Layer to Bottom Layer, tented both sides, 5 vias
v4: diameter 1.27, hole 0.711, Top Layer to Bottom Layer, tented both sides, 4 vias

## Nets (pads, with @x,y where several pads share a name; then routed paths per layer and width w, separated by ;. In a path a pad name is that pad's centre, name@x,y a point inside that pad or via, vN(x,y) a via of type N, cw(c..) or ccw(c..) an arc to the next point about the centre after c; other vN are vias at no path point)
1-WIRE: P7.1 R25.1 R26.1 U1.6 | length 12.7
  Top Layer w0.5: R25.1@30.996,62.357 R26.1@30.996,64.008 30.996,65.789 U1.6@31.12,65.913 33.216,65.913 34.232,64.897 37.109,64.897 P7.1@39.014,62.992
3CB1: C8.1 US3.1 | length 2.9
  Top Layer w0.5: US3.1@45.974,58.293 46.871,58.293 C8.1@48.268,59.69
3VSW1: C8.2 D7.2 L1.1 US3.8 | length 23.2
  Top Layer w0.254: US3.8@51.374,58.293 52.103,58.293 52.412,57.984 53.023,57.984 53.442,58.403 53.442,58.572 53.467,58.598 D7.2@55.499,58.598 ; L1.1@65.991,61.087 L1.1@67.691,61.087
  Top Layer w0.5: C8.2@49.268,59.69 49.977,59.69 US3.8@51.374,58.293 ; D7.2@55.499,58.598 55.499,58.547 57.658,56.388 62.738,56.388 65.991,59.641 L1.1@65.991,61.087
5V: C7.2 C9.2 C13.1 F1.1 J1.6 L1.2 P2.1 P2.2 P2.3 P3.1 P4.1 P8.9 P9.9 Q2.2 R1.2 R2.1 R3.1 R4.2 R8.1 R9.1 R10.1 R11.1 R12.1 R13.1 R14.1 R15.1 R18.1 R19.1 R20.2 R24.1 R25.2 R28.2 R29.2 R35.2 R37.2 R42.2 R43.2 R48.2 R49.2 RVCC.1 US1.5 US1.17 US1.27 US1.38 US2.8 US3.4 | length 278.6
  Top Layer w0.254: P8.9@31.42,51.618 32.563,51.618 32.588,51.593 32.588,49.327 29.261,45.999 29.261,39.147 30.378,38.029 P9.9@31.42,38.029 32.487,38.029 32.512,38.004 32.512,35.56 32.995,35.077 35.56,35.077 36.703,33.934 36.703,31.107 J1.6@34.98,29.384 ; Q2.2@33.39,62.423 Q2.2@32.959,62.423 ; 35.941,34.696 35.941,34.849 38.875,37.782 39.205,37.782 39.522,38.1 v1(39.522,41.199) ; v1(36.83,64.27) 34.806,64.27 34.366,63.83 Q2.2@32.959,62.423 ; US3.4@45.974,54.483 44.907,54.483 44.882,54.508 44.882,58.877 45.136,59.131 v1(45.552,59.131) 46.457,59.131 46.83,59.131 46.855,59.157 C9.2@46.855,59.69 v2(46.855,60.19) ; R24.1@58.42,58.666 58.42,59.563 ; L1.2@61.491,61.087 L1.2@63.191,61.087 ; Q2.2@32.959,62.423 32.893,62.357 R25.2@31.996,62.357 Q2.2@32.959,62.423
  Top Layer w0.5: R25.2@31.996,62.357 33.324,62.357 33.363,62.396 F1.1@33.363,60.833 ; v2(46.855,60.19) 47.866,61.201 L1.2@61.595,61.201 ; R24.1@58.42,58.666 58.42,59.563 59.944,61.087 L1.2@61.491,61.087 61.595,61.191 C13.1@61.595,66.929 ; P3.1@63.17,32.536 P4.1@67.996,32.536
  Mid-Layer 1 w0.254: v1(36.83,64.27) v1(36.83,66.294) ; v1(42.418,59.131) 45.136,59.131 v1(45.552,59.131)
  Mid-Layer 3 w0.254: v1(36.83,66.294) 39.599,66.294 40.919,64.973 40.919,60.63 v1(42.418,59.131) ; v1(39.522,41.199) 38.964,41.758 38.964,50.063 37.567,51.46 37.567,54.927 37.986,55.347 39.98,55.347 40.259,55.626 41.453,55.626 v1@43.07,54.009 ; v1(43.061,54) 43.99,53.071 v1(47.828,53.071)
  Bottom Layer w0.254: R42.2@35.806,43.561 35.806,44.088 ; R35.2@35.806,46.609 35.806,47.015 36.5,47.709 36.5,48.539 35.806,49.233 R28.2@35.806,49.657 ; R49.2@35.933,60.071 35.933,60.401 36.627,61.095 36.627,61.925 36.06,62.492 R43.2@36.06,62.992 36.06,63.5 v1(36.83,64.27) ; R35.2@35.992,46.553 35.946,46.507 35.946,45.745 35.992,45.699 36.373,45.699 36.398,45.674 36.398,44.45 36.036,44.088 35.806,44.088 ; R29.2@36.06,69.088 36.06,68.732 36.754,68.039 36.754,67.269 36.06,66.575 R37.2@36.06,66.294 v1(36.83,66.294) ; v1(39.522,41.199) 39.091,40.767 38.362,40.767 R48.2@37.338,41.791 37.228,41.791 36.398,42.621 34.652,42.621 34.214,43.059 34.214,44.063 34.239,44.088 35.806,44.088 ; R3.1@43.061,44.069 43.061,44.467 42.367,45.161 42.367,45.991 43.061,46.685 R4.2@43.061,47.117 43.061,47.49 42.164,48.387 42.164,49.268 R1.2@43.061,50.165 ; v1@43.061,54.018 v1(43.061,54) R1.2@43.061,50.165 ; US1.5@45.989,49.238 47.015,49.238 47.046,49.208 47.046,48.928 47.917,48.057 47.968,48.057 48.463,48.552 48.463,52.436 v1(47.828,53.071) ; v2(46.855,60.19) 49.284,60.19 50.165,59.309 R20.2@50.165,58.793 50.554,58.793 50.927,58.42 50.927,57.468 51.321,57.074 51.664,57.074 51.689,57.048 US1.17@51.689,55.738 51.689,54.623 50.381,53.315 50.381,51.04 50.8,50.621 54.483,50.621 ; C7.2@46.99,58.793 46.99,60.071 46.845,60.216 US2.8@45.552,60.216 v1(45.552,59.131) 45.552,58.227 45.428,58.102 43.379,58.102 43.061,57.785 R19.1@43.061,53.213 R18.1@43.061,51.689 R1.2@43.061,50.165 ; R2.1@51.046,42.545 51.562,42.545 52.489,43.472 US1.38@52.489,44.338 52.489,47.282 54.483,49.276 54.483,50.621 ; US1.27@57.389,50.838 56.667,50.838 56.451,50.621 54.483,50.621
  Bottom Layer w0.5: J1.6@34.98,29.384 36.115,29.384 37.473,30.742 R8.1@38.989,30.742 R9.1@41.275,30.742 R10.1@43.815,30.742 R11.1@46.355,30.742 R12.1@48.895,30.742 R13.1@51.435,30.742 R14.1@53.975,30.742 R15.1@56.515,30.742 56.515,28.956 57.531,27.94 62.23,27.94 62.484,27.94 ; RVCC.1@62.492,28.829 62.492,27.948 62.484,27.94 ; v2(66.802,32.512) 67.31,32.512 ; P2.3@67.792,46.526 P2.2@67.792,45.526 P2.1@67.792,44.526 67.792,43.46 68.453,42.799 68.453,33.147 67.818,32.512 67.31,32.512 ; 62.484,27.94 64.262,27.94 67.31,30.988 67.31,32.512
12V: C10.2 C11.1 D5.2 P7.4 US3.7 | length 27.6
  Top Layer w0.254: C11.1@43.053,56.642 43.053,59.174 43.053,59.855 v1(44.78,61.582) ; US3.7@51.374,57.023 51.587,57.023 v1(51.587,57.582)
  Top Layer w0.5: C11.1@42.037,55.626 C11.1@43.053,56.642 43.053,59.174 C10.2@43.569,59.69
  Top Layer w1: D5.2@42.037,51.382 C11.1@42.037,55.626
  Mid-Layer 1 w0.254: v1(44.78,61.582) 48.12,61.582 P7.4@49.53,62.992
  Bottom Layer w0.254: P7.4@49.53,62.992 50.673,62.992 50.698,62.967 50.698,61.366 51.587,60.477 v1(51.587,57.582)
A: P6.1 R12A.1 R23.2 S2.8 | length 15.9
  Top Layer w0.5: R23.2@57.15,39.489 60.237,42.576 P6.1@60.237,44.197 ; v2(57.912,40.259) v2(65.278,40.259)
  Bottom Layer w0.5: v2(57.912,40.259) 58.666,40.259 R12A.1@58.801,40.124 ; S2.8@65.278,38.608 v2(65.278,40.259)
ANALOG: D1.2 R6.1 R7.2 US1.35 | length 5.3
  Bottom Layer w0.5: US1.35@54.864,44.313 US1.35@54.889,44.338 54.889,42.012 55.237,41.664 R7.2@55.237,41.275 55.237,40.976 D1.2@56.462,39.751
B: P6.2 R22.2 S2.4 | length 37.6
  Top Layer w0.5: R22.2@57.15,44.839 57.92,44.839 60.237,47.156 P6.2@60.237,47.697 61.142,47.697 63.246,45.593 65.024,45.593 66.802,43.815 66.802,40.005 65.659,38.862 60.325,38.862 59.055,37.592 59.055,30.353 60.452,28.956 v2(61.468,28.956)
  Bottom Layer w0.5: v2(61.468,28.956) S2.4@61.468,30.988
DE: R21.1 US1.13 US2.3 | length 8.9
  Bottom Layer w0.254: US2.3@44.252,56.116 44.252,57.15 44.608,57.506 46.152,57.506 46.457,57.201 48.121,57.201 48.489,56.832 US1.13@48.489,55.738
  Bottom Layer w0.5: US1.13@48.489,55.738 48.489,57.768 R21.1@48.514,57.793
DI1: C17.2 R29.1 R31.2 US1.19 | length 37.8
  Mid-Layer 1 w0.254: v1(34.265,67.818) 49.987,67.818 51.283,66.523 51.283,59.093 v1(53.035,57.34)
  Mid-Layer 3 w0.254: v1(29.54,68.174) 29.896,67.818 v1(34.265,67.818)
  Bottom Layer w0.254: v1(29.54,68.174) 29.54,67.691 R31.2@29.726,67.691 ; R29.1@35.06,69.088 35.06,68.377 C17.2@35.06,67.818 ; v1(53.035,57.34) 53.035,56.997 53.289,56.744 US1.19@53.289,55.738 ; C17.2@35.06,67.818 v1(34.265,67.818) 34.392,67.691 C17.2@35.06,67.691 C17.2@35.06,67.818
DI2: C21.2 R37.1 R39.2 US1.20 | length 40.4
  Top Layer w0.254: v1(52.654,58.42) 52.73,58.496 52.73,59.69 53.518,60.477 v1(54.432,60.477)
  Bottom Layer w0.254: R39.2@29.726,64.262 29.726,63.81 30.162,63.373 32.842,63.373 32.842,65.38 33.237,65.774 33.846,65.774 34.366,66.294 R37.1@35.06,66.294 35.06,65.948 36.06,64.948 C21.2@36.06,64.643 36.085,65.176 54.026,65.176 54.432,64.77 v1(54.432,60.477) ; v1(52.654,58.42) 54.089,56.985 US1.20@54.089,55.738
DI3: C25.2 R43.1 R45.2 US1.21 | length 37.6
  Mid-Layer 1 w0.254: v1(29.197,61.214) 30.264,62.281 34.696,62.281 v1(35.06,62.281) ; v1(34.163,57.175) 34.544,56.794 47.527,56.794 47.811,56.509 54.528,56.509 v1(55.067,57.048)
  Mid-Layer 3 w0.254: v1(34.163,57.175) 34.696,57.709 34.696,62.281 v1(35.06,62.281)
  Bottom Layer w0.254: v1(29.197,61.214) R45.2@29.726,61.214 ; v1(35.06,62.281) 35.06,62.646 ; R43.1@35.06,62.992 35.06,62.646 ; C25.2@35.933,61.468 35.933,61.773 35.06,62.646 ; US1.21@54.889,55.738 54.889,56.87 v1(55.067,57.048)
DI4: C29.2 R49.1 R51.2 US1.22 | length 42.2
  Bottom Layer w0.254: R51.2@29.726,58.166 29.134,58.166 29.108,58.141 29.108,57.206 29.134,57.18 32.161,57.18 32.639,57.658 35.489,57.658 35.933,58.102 C29.2@35.933,58.547 ; R49.1@34.933,60.071 34.933,59.801 35.933,58.801 C29.2@35.933,58.547 ; US1.22@55.689,55.738 55.689,57.519 51.511,61.697 51.511,64.453 51.194,64.77 41.021,64.77 40.31,64.059 40.31,60.173 38.684,58.547 C29.2@35.933,58.547
DI5: C15.2 R28.1 R30.2 US1.42 | length 29.3
  Mid-Layer 1 w0.254: v1(29.947,50.978) 33.688,50.978 33.828,51.117 34.666,51.117 v1(34.806,50.978) ; v1(34.806,50.343) 35.332,49.817 44.773,49.817 v1(48.108,46.482)
  Mid-Layer 3 w0.254: v1(28.956,48.616) 28.956,49.987 v1(29.947,50.978)
  Bottom Layer w0.254: R30.2@28.456,48.133 28.473,48.133 v1(28.956,48.616) ; v1(34.806,50.978) v1(34.806,50.343) R28.1@34.806,49.657 34.806,49.387 35.806,48.387 C15.2@35.806,48.133 ; v1(48.108,46.482) 48.21,46.482 49.289,45.402 US1.42@49.289,44.338
DI6: C19.2 J1.1 R35.1 R38.2 US1.1 | length 53.3
  Mid-Layer 1 w0.254: v1(28.727,43.561) 32.918,43.561 v1(33.833,44.475) ; v1(33.833,45.136) 45.726,45.136 46.349,45.758 48.26,45.758 48.578,46.076 48.578,46.901 47.295,48.184 47.295,49.297 47.32,49.322 48.824,49.322 v1(51.13,47.015)
  Mid-Layer 3 w0.254: J1.1@30.298,34.37 33.833,37.904 v1(33.833,44.475) v1(33.833,45.136)
  Bottom Layer w0.254: R38.2@28.456,45.085 28.456,43.832 v1(28.727,43.561) ; v1(33.833,44.475) 33.849,44.492 35.399,44.492 35.611,44.704 C19.2@35.611,45.085 ; R35.1@34.806,46.609 34.806,46.339 35.489,45.656 35.489,45.098 35.502,45.085 C19.2@35.611,45.085 ; C19.2@35.806,45.085 C19.2@35.611,45.085 ; US1.1@45.989,46.038 47.549,46.038 47.574,46.063 47.574,46.672 47.917,47.015 v1(51.13,47.015)
DI7: C23.2 R42.1 R44.2 US1.33 | length 31.4
  Mid-Layer 3 w0.254: v1(40.208,47.422) 50.703,47.422 50.838,47.557 54.424,47.557 55.499,46.482 v1(58.649,46.482)
  Bottom Layer w0.254: R42.1@34.806,43.561 35.179,43.561 35.204,43.536 35.204,43.053 35.23,43.028 36.525,43.028 36.982,43.485 37.897,43.485 38.227,43.815 38.227,45.077 C23.2@38.989,45.077 39.883,45.077 40.208,45.402 v1(40.208,47.422) ; R44.2@37.338,45.077 38.481,45.077 ; US1.33@57.389,46.038 58.623,46.038 58.649,46.063 v1(58.649,46.482)
DI8: C27.2 R48.1 R50.2 US1.32 | length 68.8
  Mid-Layer 1 w0.254: v1(29.896,39.827) 29.896,36.195 30.378,35.712 36.043,35.712 37.008,34.747 47.104,34.747 47.6,35.242 47.6,38.887 v1(47.396,39.091)
  Mid-Layer 3 w0.254: v1(47.396,39.091) 57.887,39.091 61.722,42.926 61.722,48.387 60.96,49.149 59.36,49.149 58.674,48.463 v1(58.674,46.939)
  Bottom Layer w0.254: v1(29.896,39.827) 31.377,39.802 R50.2@31.377,39.37 ; R48.1@37.338,42.791 37.643,42.791 38.643,41.791 C27.2@38.989,41.791 40.33,41.791 41.504,40.618 41.529,38.71 47.015,38.71 47.383,39.103 v1(47.396,39.091) ; US1.32@57.389,46.838 58.318,46.939 v1(58.674,46.939)
DIP_H: C5.1 J2.9 J2.10 J2.11 J2.12 R17.1 US1.36 | length 17.8
  Bottom Layer w0.254: C5.1@51.427,40.767 51.943,40.767 52.705,41.529 52.705,42.418 53.239,42.952 53.848,42.952 54.089,43.193 US1.36@54.089,44.338
  Bottom Layer w0.5: J2.12@48.946,35.941 J2.11@51.486,35.941 ; C5.1@51.427,40.767 R17.1@51.427,39.243 51.486,39.184 J2.11@51.486,35.941 ; J2.9@56.566,35.941 J2.10@54.026,35.941 J2.11@51.486,35.941
DIP_L: C4.1 J2.13 J2.14 J2.15 J2.16 R16.1 US1.37 | length 20.5
  Bottom Layer w0.254: C4.1@48.395,40.767 48.395,41.283 48.768,41.656 51.435,41.656 52.301,42.522 52.301,42.585 US1.37@53.289,43.573 ; US1.37@53.289,43.53 US1.37@53.289,43.573 ; US1.37@53.289,44.338 US1.37@53.289,43.573
  Bottom Layer w0.5: J2.16@38.786,35.941 J2.15@41.326,35.941 J2.14@43.866,35.941 J2.13@46.406,35.941 46.406,37.254 R16.1@48.395,39.243 C4.1@48.395,40.767
DO1: R32.2 US1.23 | length 27.1
  Mid-Layer 1 w0.254: v1(33.68,55.118) 34.857,56.294 46.355,56.294 46.714,55.936 47.527,55.936 47.568,55.977 v1(56.464,55.977)
  Bottom Layer w0.254: R32.2@32.377,55.118 v1(33.68,55.118) ; v1(56.464,55.977) 57.389,55.052 US1.23@57.389,54.038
